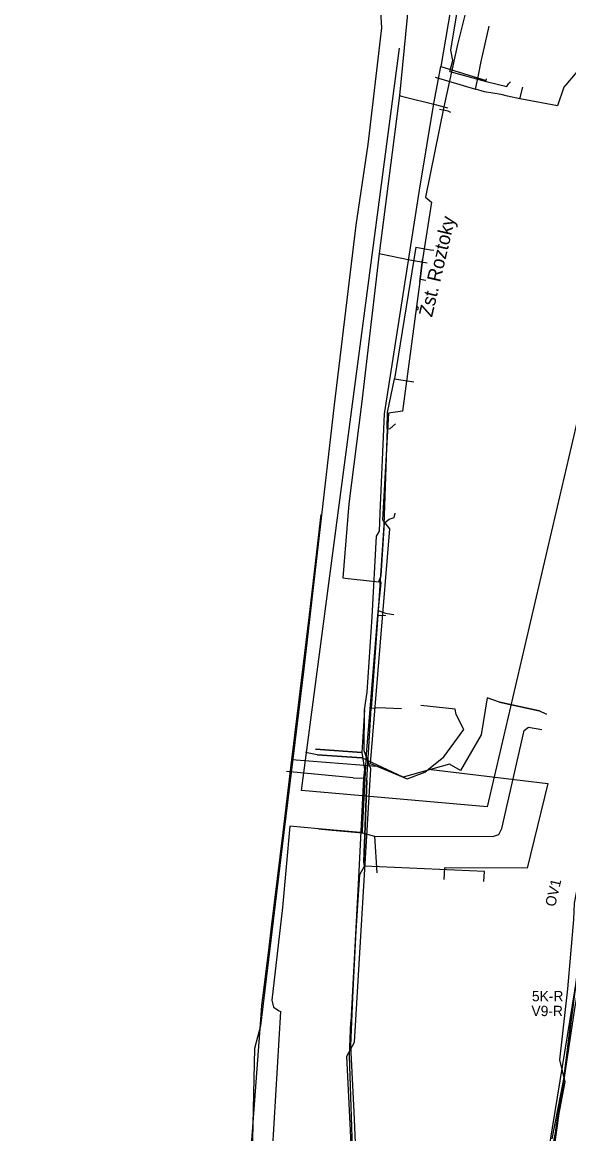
# Model space of a CAD drawing. Extents: x -748507 to -687366, y -1057342 to -1024924.
# Drawn here: x -743438.6 to -743359.2, y -1034916 to -1034754.6 of the extents above; entities that cross this region are included whole.
import ezdxf

# ---------------------------------------------------------------- set-up
doc = ezdxf.new("R2010")
doc.units = 0
for name, color, linetype in [('DK + TKK - SŽDC', 7, 'Continuous'), ('DK - Pha Holešovice - Kralupy - ČD TELEMATIKA', 7, 'Continuous'), ('PRE - NN', 7, 'Continuous'), ('PRE - VN', 7, 'Continuous'), ('Sděl MK - SŽDC', 7, 'Continuous'), ('STL - PRAŽSKÁ PLYNÁRENSKÁ', 7, 'Continuous'), ('Telefonica O2', 7, 'Continuous'), ('TK+DOK_Pha Holešovice - Kralupy', 7, 'Continuous'), ('Vedení NN - SŽDC', 7, 'Continuous'), ('Vrstva 14', 7, 'Continuous')]:
    doc.layers.add(name, color=color, linetype=linetype)

msp = doc.modelspace()

# ---------------------------------------------------------------- linework, layer by layer
at = {"layer": 'DK + TKK - SŽDC'}
for points in [[(-743359.88, -1034908.13), (-743358.27, -1034897.52), (-743358.16, -1034896.83), (-743357.95, -1034895.45), (-743357.87, -1034894.89), (-743357.32, -1034892.86)], [(-743366.85, -1034963.25), (-743363.85, -1034935.99), (-743362, -1034923.45), (-743361.01, -1034914.72), (-743359.88, -1034908.13)]]:
    msp.add_lwpolyline(points, dxfattribs=at)
at = {"layer": 'DK - Pha Holešovice - Kralupy - ČD TELEMATIKA'}
msp.add_lwpolyline([(-743377.03, -1035005.49), (-743368.34, -1034956.7), (-743353.7, -1034866.78), (-743337.71, -1034798.24), (-743336.02, -1034791), (-743346.65, -1034788.52), (-743352.11, -1034787.24), (-743371.09, -1034868.57), (-743398.01, -1034866.19), (-743383.8, -1034758.42)], dxfattribs=at)
at = {"layer": 'PRE - NN'}
for points in [[(-743373.22, -1034733.88), (-743370.85, -1034742.15), (-743371.78, -1034743.63), (-743372.91, -1034747.96), (-743375.37, -1034757.88), (-743377.36, -1034766.91), (-743380.03, -1034780.03), (-743379.17, -1034780.79), (-743380.47, -1034789.08), (-743380.84, -1034792.27), (-743383.38, -1034811.11), (-743385.42, -1034811.38), (-743386.25, -1034826.87), (-743385.25, -1034828.17), (-743388.06, -1034862.24), (-743387.08, -1034862.66)], [(-743380.79, -1034791.96), (-743380.53, -1034789.48), (-743380.47, -1034789.08)], [(-743380.84, -1034792.27), (-743380.79, -1034791.96)], [(-743380.79, -1034791.96), (-743379.96, -1034792.11)], [(-743399.42, -1034861.69), (-743399.38, -1034861.33), (-743396.86, -1034840.66), (-743396.09, -1034834.04), (-743395.17, -1034826.1)], [(-743379.57, -1034863.1), (-743377.38, -1034861.29), (-743374.45, -1034857.31), (-743375.58, -1034855.15), (-743375.71, -1034854.35), (-743380.69, -1034853.86)], [(-743400.71, -1034872.29), (-743399.42, -1034861.69)], [(-743399.42, -1034861.69), (-743387.08, -1034862.66)], [(-743387.08, -1034862.66), (-743382.71, -1034864.5), (-743380.1, -1034863.54), (-743379.57, -1034863.1)], [(-743379.57, -1034863.1), (-743362.24, -1034865.14)], [(-743362.24, -1034865.14), (-743365.26, -1034877.47), (-743377.28, -1034877.41), (-743377.36, -1034879.09)], [(-743402.73, -1034888.9), (-743402.38, -1034886.01), (-743400.71, -1034872.29)], [(-743403.93, -1034899.4), (-743403.78, -1034897.4), (-743403.45, -1034894.77), (-743402.73, -1034888.9)], [(-743402.18, -1034971.95), (-743402.42, -1034969.61), (-743402.92, -1034963.13), (-743403.2, -1034959.55), (-743403.95, -1034951.57), (-743404.7, -1034943.67), (-743405.05, -1034931.14), (-743405.38, -1034918.95), (-743403.93, -1034899.4)]]:
    msp.add_lwpolyline(points, dxfattribs=at)
at = {"layer": 'PRE - VN'}
msp.add_lwpolyline([(-743386.96, -1034746.84), (-743386.43, -1034755.47), (-743388.39, -1034772.38), (-743390.15, -1034784.1), (-743393.27, -1034810.2), (-743395.46, -1034829.17), (-743397.7, -1034848.5), (-743400.85, -1034874.24), (-743403.97, -1034900.34), (-743404.87, -1034903.61), (-743405.28, -1034923.47), (-743405.06, -1034930.58), (-743404.67, -1034943.4), (-743404.49, -1034946.05), (-743403.07, -1034959.38), (-743402.37, -1034965), (-743400.61, -1034980.75), (-743400.4, -1034982.64), (-743400.59, -1034983.77)], dxfattribs=at)
at = {"layer": 'Sděl MK - SŽDC'}
msp.add_lwpolyline([(-743361.61, -1034916.75), (-743359.94, -1034908.08), (-743358.94, -1034899.88), (-743357.7, -1034890.72), (-743355.82, -1034883.69), (-743355.02, -1034878.21), (-743353.87, -1034874.78), (-743352.91, -1034869.19), (-743330.54, -1034874.5), (-743317.61, -1034878.3), (-743316.35, -1034876.52)], dxfattribs=at)
at = {"layer": 'STL - PRAŽSKÁ PLYNÁRENSKÁ'}
for p, q in [((-743383.49, -1034765.36), (-743378.45, -1034766.66)), ((-743386.49, -1034788.27), (-743382.31, -1034789.14)), ((-743391.71, -1034835.36), (-743387.72, -1034835.77)), ((-743386.98, -1034840.74), (-743385.77, -1034840.79)), ((-743389.22, -1034871.98), (-743388.86, -1034865.34)), ((-743395.57, -1034871.75), (-743393.59, -1034871.93)), ((-743393.51, -1034871.94), (-743389.24, -1034872.33)), ((-743389.24, -1034872.33), (-743387.42, -1034872.8)), ((-743387.42, -1034872.8), (-743387.11, -1034878.13)), ((-743402.25, -1034918.57), (-743401.05, -1034898.28))]:
    msp.add_line(p, q, dxfattribs=at)
for points in [[(-743383.84, -1034743.37), (-743382.82, -1034748.42), (-743382.68, -1034753.93), (-743383.78, -1034765.28), (-743386.74, -1034788.22), (-743389.33, -1034810.09), (-743391.16, -1034824.58), (-743392.04, -1034835.32), (-743391.71, -1034835.36), (-743387.72, -1034835.77), (-743386.79, -1034835.87), (-743386.51, -1034835.9), (-743386.57, -1034836.5), (-743386.98, -1034840.74), (-743388.62, -1034860.92), (-743388.86, -1034865.34), (-743389.22, -1034871.98), (-743389.24, -1034872.33)], [(-743383.78, -1034765.28), (-743383.49, -1034765.36), (-743378.45, -1034766.66), (-743376.84, -1034767.08)], [(-743386.74, -1034788.22), (-743386.49, -1034788.27), (-743382.31, -1034789.14), (-743379.77, -1034789.57)], [(-743386.79, -1034835.87), (-743386.46, -1034834.95), (-743385.98, -1034827.33), (-743385.32, -1034826.8), (-743384.59, -1034826.54), (-743384.45, -1034825.92)], [(-743387.42, -1034872.8), (-743370.26, -1034872.88), (-743369.36, -1034872.58), (-743368.92, -1034871.69), (-743365.71, -1034857.46), (-743365.08, -1034856.99), (-743363.15, -1034857.33)], [(-743389.24, -1034872.33), (-743389.51, -1034872.3), (-743395.57, -1034871.75), (-743399.74, -1034871.36), (-743400.81, -1034883.15), (-743402.35, -1034896.6), (-743402.11, -1034897.63), (-743401.28, -1034898.16), (-743401.05, -1034898.28)]]:
    msp.add_lwpolyline(points, dxfattribs=at)
at = {"layer": 'Telefonica O2'}
for points in [[(-743394.52, -1034708.48), (-743392.65, -1034711.81), (-743390.18, -1034716), (-743384.99, -1034725.02), (-743381.87, -1034731.08), (-743375.37, -1034734.92), (-743371.06, -1034740.06), (-743374.51, -1034746.32), (-743376.06, -1034750.8), (-743377.8, -1034761.09)], [(-743376.5, -1034761.8), (-743376.04, -1034760.21), (-743376.37, -1034758.69), (-743375.23, -1034751.96), (-743374.76, -1034750), (-743374.36, -1034748.33), (-743372.86, -1034745.29), (-743368.92, -1034739.35), (-743369.61, -1034738.97), (-743373.22, -1034736.99)], [(-743355.16, -1034750.99), (-743357.18, -1034760.85), (-743359.92, -1034764.05), (-743360.87, -1034766.8), (-743365.52, -1034765.89)], [(-743371.94, -1034760.36), (-743370.78, -1034755.22)], [(-743372.38, -1034762.55), (-743371.94, -1034760.36)], [(-743388.89, -1034854.48), (-743388.5, -1034851.88), (-743387.76, -1034840.96), (-743387.12, -1034829.26), (-743386.72, -1034828.51), (-743386.62, -1034825.9), (-743385.96, -1034811.5), (-743380.88, -1034779.04), (-743378.82, -1034766.44), (-743377.8, -1034761.09)], [(-743377.8, -1034761.09), (-743371.22, -1034763.08), (-743371.16, -1034762.85)], [(-743376.5, -1034761.8), (-743371.22, -1034763.23), (-743368.23, -1034763.96), (-743367.95, -1034763.6), (-743367.68, -1034763.29)], [(-743378.62, -1034762.61), (-743372.75, -1034764.34)], [(-743372.75, -1034764.34), (-743372.38, -1034762.55)], [(-743371.45, -1034764.73), (-743372.75, -1034764.34)], [(-743369.05, -1034765.16), (-743371.45, -1034764.73)], [(-743368.1, -1034765.36), (-743369.05, -1034765.16)], [(-743366.33, -1034765.77), (-743365.88, -1034764.08)], [(-743366.33, -1034765.77), (-743368.1, -1034765.36)], [(-743365.52, -1034765.89), (-743366.33, -1034765.77)], [(-743376.33, -1034767.76), (-743376.74, -1034767.58), (-743377.99, -1034767.33)], [(-743381.42, -1034787.32), (-743384.53, -1034806.42)], [(-743381.42, -1034787.32), (-743379.31, -1034787.7), (-743378.83, -1034787.74)], [(-743385.6, -1034813.63), (-743385.52, -1034811.31), (-743384.53, -1034806.42)], [(-743384.53, -1034806.42), (-743381.74, -1034806.86)], [(-743385.6, -1034813.63), (-743386.08, -1034827.65), (-743386.89, -1034840.04)], [(-743385.6, -1034813.63), (-743385.19, -1034813.65), (-743384.4, -1034812.96)], [(-743386.89, -1034840.04), (-743387.92, -1034854.21)], [(-743386.89, -1034840.04), (-743385.83, -1034840.42)], [(-743385.83, -1034840.42), (-743385.6, -1034840.5), (-743384.64, -1034840.65)], [(-743362.4, -1034855.13), (-743363.5, -1034854.6), (-743369.3, -1034853.35), (-743371.06, -1034852.72), (-743371.93, -1034858.12), (-743374.92, -1034863.26), (-743376.54, -1034862.36), (-743383.29, -1034864.24), (-743389.28, -1034861.44), (-743395.74, -1034861.01), (-743397.43, -1034860.67)], [(-743369.3, -1034853.35), (-743363.5, -1034854.6)], [(-743389.87, -1034937.6), (-743390.23, -1034929.27), (-743391.43, -1034904.77), (-743390.34, -1034902.72), (-743387.96, -1034863.05), (-743388.94, -1034860.42), (-743388.89, -1034854.48)], [(-743388.89, -1034854.48), (-743389.27, -1034860.64)], [(-743388.87, -1034877.16), (-743388.99, -1034876.55), (-743388.54, -1034864.73), (-743387.92, -1034854.21)], [(-743387.92, -1034854.21), (-743386.93, -1034854.11), (-743383.49, -1034854.27)], [(-743389.27, -1034860.64), (-743395.98, -1034860.16)], [(-743395.98, -1034860.16), (-743389.27, -1034860.64)], [(-743395.74, -1034861.01), (-743389.28, -1034861.44)], [(-743389.27, -1034860.64), (-743388.9, -1034863.15)], [(-743390.55, -1034864.32), (-743400.23, -1034863.4)], [(-743388.9, -1034863.15), (-743389.05, -1034864.4)], [(-743389.05, -1034864.4), (-743389.74, -1034878.86), (-743390.86, -1034899.79)], [(-743390.55, -1034864.32), (-743389.05, -1034864.4)], [(-743388.54, -1034864.73), (-743388.99, -1034876.55)], [(-743341.91, -1034979.19), (-743342.25, -1034981.58), (-743342.56, -1034983.83), (-743350.69, -1034983.41), (-743371.16, -1034978.54), (-743375.61, -1034975.42), (-743381.06, -1034970.27), (-743382.84, -1034967.47), (-743385.69, -1034961.73), (-743388.96, -1034952), (-743389.47, -1034940), (-743389.81, -1034926.32), (-743390.4, -1034912.82), (-743390.87, -1034903.26), (-743390.6, -1034896.21), (-743390.07, -1034886.54), (-743389.54, -1034878.36), (-743388.87, -1034877.16)], [(-743371.54, -1034879.37), (-743371.46, -1034877.94), (-743388.87, -1034877.16)], [(-743375.53, -1034978.21), (-743376.05, -1034975.38), (-743381.68, -1034970.8), (-743386.27, -1034962.91), (-743389.65, -1034950.78), (-743389.85, -1034941.8), (-743391.08, -1034904.63), (-743390.86, -1034899.79)]]:
    msp.add_lwpolyline(points, dxfattribs=at)
at = {"layer": 'TK+DOK_Pha Holešovice - Kralupy'}
msp.add_lwpolyline([(-743353.01, -1034869.17), (-743353.92, -1034874.82), (-743358.33, -1034895.34), (-743359.98, -1034908.21), (-743362.03, -1034922.73), (-743365.6, -1034955.73), (-743367.85, -1034965.91), (-743368.67, -1034969.72), (-743374.54, -1034999.58), (-743381.09, -1035030.83), (-743388.05, -1035062.38), (-743393.89, -1035088.93), (-743398.82, -1035111.05), (-743405.79, -1035141.35), (-743412.61, -1035171.74), (-743420.68, -1035207.17), (-743424.57, -1035211.33), (-743427.48, -1035221.1), (-743428.53, -1035225.12), (-743433.03, -1035244.31), (-743438.01, -1035261.61), (-743438.58, -1035265.06)], dxfattribs=at)
at = {"layer": 'Vedení NN - SŽDC'}
for points in [[(-743413.03, -1035172.29), (-743402.89, -1035127.87), (-743393.84, -1035087.43), (-743386.11, -1035053.28), (-743381.72, -1035033.62), (-743376.3, -1035007.33), (-743371.61, -1034985.85), (-743373.14, -1034982.41), (-743368.87, -1034972.33), (-743367.76, -1034965.58), (-743365.78, -1034955.64), (-743364.53, -1034942.66), (-743362.23, -1034921.42), (-743359.73, -1034908.49), (-743360.53, -1034905.29), (-743359.37, -1034894.97), (-743358.47, -1034884.91), (-743358.38, -1034882.55), (-743357.07, -1034875.75), (-743356.19, -1034872.57), (-743353.64, -1034869.52), (-743352.92, -1034869.25), (-743335.08, -1034793.5), (-743315.44, -1034713.05)], [(-743368.87, -1034972.33), (-743367.76, -1034965.58), (-743365.78, -1034955.64), (-743364.53, -1034942.66), (-743362.23, -1034921.42), (-743359.73, -1034908.49), (-743360.53, -1034905.29), (-743359.37, -1034894.97), (-743358.47, -1034884.91), (-743358.38, -1034882.55), (-743357.07, -1034875.75)]]:
    msp.add_lwpolyline(points, dxfattribs=at)

# ---------------------------------------------------------------- texts
at = {"layer": 'DK + TKK - SŽDC'}
for s, p in [('5K-R', (-743364.57, -1034896.78)), ('V9-R', (-743364.64, -1034898.93))]:
    msp.add_text(s, height=1.5, dxfattribs=at).set_placement(p)
at = {"layer": 'Vedení NN - SŽDC'}
msp.add_text('OV1', height=1.5, rotation=76.8337, dxfattribs=at).set_placement((-743361.21, -1034883.13))
at = {"layer": 'Vrstva 14'}
msp.add_text('Žst. Roztoky', height=2, rotation=76.8478, dxfattribs=at).set_placement((-743379.08, -1034797.55))

doc.saveas('drawing.dxf')
